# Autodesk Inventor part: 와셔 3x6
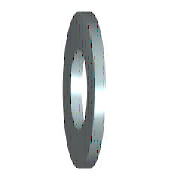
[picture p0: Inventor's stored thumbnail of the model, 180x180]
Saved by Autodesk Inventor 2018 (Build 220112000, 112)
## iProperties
IsCustomPart: 0
Created: 2012-02
Part Number: 와셔 3x6
Material: 강철, 연강
Description: 평면 와셔
Document SubType Name: Modeling
Standard: KS B 1326
Designer: mduedu
Standards Organization: KS
Language: ko-KR
Size Designation: 3x6
Categories: <MemberInstance><Categories><Category DisplayName="조임쇠" InternalName="e4da775c-781d-43d5-af7c-5136215cf5a6" Mnemonic="FSTN"><Category DisplayName="와셔" InternalN
Density: 7.86 g/cm^3
Mass: 0.0795112 g
Surface Area: 0.54915 cm^2
Volume: 0.0101159 cm^3
Appearance: 파란색 - 벽 페인트 - 광택
Author: mduedu
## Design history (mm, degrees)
sketch "스케치"
  geometry: C1 r 3 at (0, 0); C2 r 1.6 at (0, 0); 1 further point
  constraints: 2 centre point, 2 coincident
  dimensions: "d0" = 3.2 diameter of C2 (= SD1); "d1" = 6 diameter of C1 (= SD2)
extrude "본체" new body sketch "스케치" distance "d2" = 0.5 (= SD); taper "d3" = 0 deg
workaxis "Work Axis1"
workplane "Work Plane1"
body "Solid1"
other parameters: "SD1" = 3.2 [user parameter; used in 1 equation term], "SD2" = 6 [user parameter; used in 1 equation term], "SD" = 0.5 [user parameter; used in 1 equation term], "d4" = 0, "d5" = 0, "d6" = 0, "d7" = 0, "NND" = 3 [user parameter]
